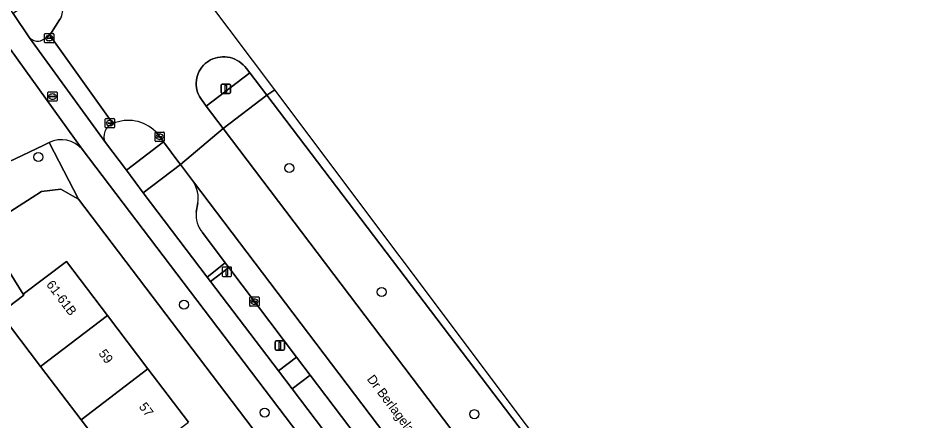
# Model space of a CAD drawing. Extents: x 159664 to 160323, y 385312 to 386115.
# Drawn here: x 160147.9 to 160245, y 385864 to 385907.3 of the extents above; entities that cross this region are included whole.
import ezdxf

# ---------------------------------------------------------------- set-up
doc = ezdxf.new("R2010")
doc.units = 0
for name, color, linetype in [('IMGEO_Berm_groen', 7, 'Continuous'), ('IMGEO_Boom', 7, 'Continuous'), ('IMGEO_Erf', 7, 'Continuous'), ('IMGEO_Fietspad_gesloten', 7, 'Continuous'), ('IMGEO_Kolk', 7, 'Continuous'), ('IMGEO_Laadpaal', 7, 'Continuous'), ('IMGEO_Lichtmast', 7, 'Continuous'), ('IMGEO_Openbare_ruimte_label', 7, 'Continuous'), ('IMGEO_Pand', 7, 'Continuous'), ('IMGEO_Pand_nummerreeks', 7, 'Continuous'), ('IMGEO_Parkeervlak_open', 7, 'Continuous'), ('IMGEO_Rijbaan_lokaal_gesloten', 7, 'Continuous'), ('IMGEO_Rijbaan_lokaal_open', 7, 'Continuous'), ('IMGEO_Rioolput', 7, 'Continuous'), ('IMGEO_Verkeerseiland_groen', 7, 'Continuous'), ('IMGEO_Voetpad_open', 7, 'Continuous')]:
    doc.layers.add(name, color=color, linetype=linetype)

msp = doc.modelspace()

# ---------------------------------------------------------------- linework, layer by layer
at = {"layer": 'IMGEO_Berm_groen'}
for points in [[(160174.614, 385899.039), (160169.921, 385895.45), (160202.923, 385851.883), (160207.751, 385855.425)], [(160170.512, 385880.51), (160168.561, 385878.986), (160175.871, 385869.409), (160177.807, 385870.864)], [(160179.262, 385868.942), (160177.327, 385867.463), (160185.75, 385856.345), (160187.67, 385857.825)]]:
    msp.add_lwpolyline(points, close=True, dxfattribs=at)
for points in [[(160166.706, 385889.723), (160165.321, 385891.586), (160161.323, 385888.557), (160168.182, 385879.472), (160170.13, 385881.015), (160167.67, 385884.268)], [(160167.013, 385886.47), (160167.181, 385887.448)]]:
    msp.add_lwpolyline(points, dxfattribs=at)
for centre, radius, start, end in [((160163.974, 385887.965), 3.249, 350.83368, 32.75318), ((160169.866, 385886.122), 2.874, 173.04987, 220.17667)]:
    msp.add_arc(centre, radius, start, end, dxfattribs=at)
at = {"layer": 'IMGEO_Boom'}
for centre in [(160150.028, 385892.391), (160177.009, 385891.198), (160186.938, 385877.865), (160165.693, 385876.504), (160174.362, 385864.905), (160196.921, 385864.728)]:
    msp.add_circle(centre, 0.489, dxfattribs=at)
at = {"layer": 'IMGEO_Erf'}
for points in [[(160260.143, 385748.478), (160154.34, 385887.843), (160153.697, 385888.214), (160152.472, 385888.921), (160150.373, 385888.694), (160144.032, 385884.624)], [(160145.125, 385882.921), (160148.409, 385877.638), (160153.059, 385881.162), (160157.479, 385875.33), (160161.823, 385869.601), (160166.166, 385863.87)], [(160158.979, 385858.412), (160154.631, 385864.138), (160150.282, 385869.865), (160145.932, 385875.592)]]:
    msp.add_lwpolyline(points, dxfattribs=at)
at = {"layer": 'IMGEO_Fietspad_gesloten'}
msp.add_lwpolyline([(160201.804, 385835.617), (160197.359, 385841.045), (160186.137, 385855.863), (160185.75, 385856.345), (160177.327, 385867.463), (160175.871, 385869.409), (160168.561, 385878.986), (160168.182, 385879.472), (160161.323, 385888.557), (160159.511, 385890.971), (160157.24, 385893.946), (160149.098, 385905.226), (160147.316, 385907.817), (160144.932, 385911.316), (160142.935, 385909.961), (160147.03, 385903.951), (160154.766, 385893.221), (160263.854, 385749.476), (160272.35, 385738.304), (160298.51, 385703.942), (160300.884, 385700.823)], dxfattribs=at)
at = {"layer": 'IMGEO_Kolk'}
for p, q in [((160150.713, 385904.753), (160150.713, 385905.605)), ((160150.788, 385905.679), (160151.64, 385905.679)), ((160151.201, 385905.459), (160151.226, 385905.459)), ((160151.714, 385905.605), (160151.714, 385904.753)), ((160151.64, 385904.679), (160150.788, 385904.679)), ((160150.972, 385905.173), (160150.972, 385905.185)), ((160151.41, 385905.136), (160151.012, 385905.136)), ((160151.015, 385905.222), (160151.413, 385905.222)), ((160151.224, 385904.899), (160151.199, 385904.899)), ((160151.456, 385905.185), (160151.456, 385905.173)), ((160157.237, 385895.612), (160157.237, 385896.464)), ((160157.312, 385896.538), (160158.164, 385896.538)), ((160157.496, 385896.032), (160157.496, 385896.044)), ((160157.934, 385895.995), (160157.536, 385895.995)), ((160157.539, 385896.081), (160157.937, 385896.081)), ((160157.748, 385895.758), (160157.723, 385895.758)), ((160157.725, 385896.318), (160157.75, 385896.318)), ((160157.98, 385896.044), (160157.98, 385896.032)), ((160158.238, 385896.464), (160158.238, 385895.612)), ((160158.164, 385895.538), (160157.312, 385895.538)), ((160162.579, 385894.147), (160162.579, 385894.999)), ((160162.654, 385895.073), (160163.506, 385895.073)), ((160163.067, 385894.853), (160163.092, 385894.853)), ((160163.58, 385894.999), (160163.58, 385894.147)), ((160163.506, 385894.073), (160162.654, 385894.073)), ((160162.838, 385894.567), (160162.838, 385894.579)), ((160163.276, 385894.53), (160162.878, 385894.53)), ((160162.881, 385894.616), (160163.279, 385894.616)), ((160163.09, 385894.293), (160163.065, 385894.293)), ((160163.322, 385894.579), (160163.322, 385894.567)), ((160172.834, 385877.338), (160173.686, 385877.338)), ((160172.759, 385876.412), (160172.759, 385877.264)), ((160173.686, 385876.338), (160172.834, 385876.338)), ((160173.018, 385876.832), (160173.018, 385876.844)), ((160173.456, 385876.795), (160173.058, 385876.795)), ((160173.061, 385876.881), (160173.459, 385876.881)), ((160173.27, 385876.558), (160173.245, 385876.558)), ((160173.247, 385877.118), (160173.272, 385877.118)), ((160173.502, 385876.844), (160173.502, 385876.832)), ((160173.76, 385877.264), (160173.76, 385876.412))]:
    msp.add_line(p, q, dxfattribs=at)
for points in [[(160150.713, 385904.753), (160150.713, 385905.605)], [(160150.788, 385905.679), (160151.64, 385905.679)], [(160151.714, 385905.605), (160151.714, 385904.753)], [(160151.64, 385904.679), (160150.788, 385904.679)], [(160157.237, 385895.612), (160157.237, 385896.464)], [(160157.312, 385896.538), (160158.164, 385896.538)], [(160158.238, 385896.464), (160158.238, 385895.612)], [(160158.164, 385895.538), (160157.312, 385895.538)], [(160162.579, 385894.147), (160162.579, 385894.999)], [(160162.654, 385895.073), (160163.506, 385895.073)], [(160163.58, 385894.999), (160163.58, 385894.147)], [(160163.506, 385894.073), (160162.654, 385894.073)], [(160172.834, 385877.338), (160173.686, 385877.338)], [(160172.759, 385876.412), (160172.759, 385877.264)], [(160173.686, 385876.338), (160172.834, 385876.338)], [(160173.76, 385877.264), (160173.76, 385876.412)]]:
    msp.add_lwpolyline(points, dxfattribs=at)
for centre, radius, start, end in [((160150.79, 385905.603), 0.0765, 91.55205, 178.44795), ((160150.79, 385905.603), 0.0765, 91.55205, 178.44795), ((160151.638, 385905.603), 0.0765, 1.55205, 88.44795), ((160151.638, 385905.603), 0.0765, 1.55205, 88.44795), ((160150.79, 385904.755), 0.0765, 181.55205, 268.44795), ((160150.79, 385904.755), 0.0765, 181.55205, 268.44795), ((160151.012, 385905.182), 0.0403, 85.87752, 175.75265), ((160151.009, 385905.172), 0.0366, 178.93798, 274.71019), ((160151.413, 385905.179), 0.043, 264.86636, 352.45326), ((160151.417, 385905.184), 0.0386, 1.73085, 96.63898), ((160151.638, 385904.755), 0.0765, 271.55205, 358.44795), ((160151.638, 385904.755), 0.0765, 271.55205, 358.44795), ((160157.314, 385896.462), 0.0765, 91.55205, 178.44795), ((160157.314, 385896.462), 0.0765, 91.55205, 178.44795), ((160157.536, 385896.041), 0.0403, 85.87752, 175.75265), ((160157.533, 385896.031), 0.0366, 178.93798, 274.71019), ((160157.937, 385896.038), 0.043, 264.86636, 352.45326), ((160157.941, 385896.043), 0.0386, 1.73085, 96.63898), ((160158.162, 385896.462), 0.0765, 1.55205, 88.44795), ((160158.162, 385896.462), 0.0765, 1.55205, 88.44795), ((160157.314, 385895.614), 0.0765, 181.55205, 268.44795), ((160157.314, 385895.614), 0.0765, 181.55205, 268.44795), ((160158.162, 385895.614), 0.0765, 271.55205, 358.44795), ((160158.162, 385895.614), 0.0765, 271.55205, 358.44795), ((160162.656, 385894.997), 0.0765, 91.55205, 178.44795), ((160162.656, 385894.997), 0.0765, 91.55205, 178.44795), ((160163.504, 385894.997), 0.0765, 1.55205, 88.44795), ((160163.504, 385894.997), 0.0765, 1.55205, 88.44795), ((160162.656, 385894.149), 0.0765, 181.55205, 268.44795), ((160162.656, 385894.149), 0.0765, 181.55205, 268.44795), ((160162.878, 385894.576), 0.0403, 85.87752, 175.75265), ((160162.875, 385894.566), 0.0366, 178.93798, 274.71019), ((160163.279, 385894.573), 0.043, 264.86636, 352.45326), ((160163.283, 385894.578), 0.0386, 1.73085, 96.63898), ((160163.504, 385894.149), 0.0765, 271.55205, 358.44795), ((160163.504, 385894.149), 0.0765, 271.55205, 358.44795), ((160172.836, 385877.262), 0.0765, 91.55205, 178.44795), ((160172.836, 385877.262), 0.0765, 91.55205, 178.44795), ((160173.684, 385877.262), 0.0765, 1.55205, 88.44795), ((160173.684, 385877.262), 0.0765, 1.55205, 88.44795), ((160172.836, 385876.414), 0.0765, 181.55205, 268.44795), ((160172.836, 385876.414), 0.0765, 181.55205, 268.44795), ((160173.058, 385876.841), 0.0403, 85.87752, 175.75265), ((160173.055, 385876.831), 0.0366, 178.93798, 274.71019), ((160173.459, 385876.838), 0.043, 264.86636, 352.45326), ((160173.463, 385876.843), 0.0386, 1.73085, 96.63898), ((160173.684, 385876.414), 0.0765, 271.55205, 358.44795), ((160173.684, 385876.414), 0.0765, 271.55205, 358.44795)]:
    msp.add_arc(centre, radius, start, end, dxfattribs=at)
for centre, major_axis, ratio, start_param, end_param in [((160151.2, 385905.179), (-0.387, 0.002), 0.722429, 4.712389, 7.853982), ((160151.225, 385905.179), (-0.39, 0.002), 0.717154, 1.570796, 4.712389), ((160157.724, 385896.038), (-0.387, 0.002), 0.722429, 4.712389, 7.853982), ((160157.749, 385896.038), (-0.39, 0.002), 0.717154, 1.570796, 4.712389), ((160163.066, 385894.573), (-0.387, 0.002), 0.722429, 4.712389, 7.853982), ((160163.091, 385894.573), (-0.39, 0.002), 0.717154, 1.570796, 4.712389), ((160173.246, 385876.838), (-0.387, 0.002), 0.722429, 4.712389, 7.853982), ((160173.271, 385876.838), (-0.39, 0.002), 0.717154, 1.570796, 4.712389)]:
    msp.add_ellipse(centre, major_axis=major_axis, ratio=ratio, start_param=start_param, end_param=end_param, dxfattribs=at)
at = {"layer": 'IMGEO_Laadpaal'}
for p, q in [((160169.799, 385880.472), (160169.799, 385879.631)), ((160169.799, 385880.472), (160169.799, 385879.631)), ((160170.715, 385880.556), (160169.874, 385880.556)), ((160170.715, 385880.556), (160169.874, 385880.556)), ((160170.799, 385879.64), (160170.799, 385880.481)), ((160170.799, 385879.64), (160170.799, 385880.481)), ((160169.883, 385879.556), (160170.724, 385879.556)), ((160169.883, 385879.556), (160170.724, 385879.556))]:
    msp.add_line(p, q, dxfattribs=at)
msp.add_lwpolyline([(160170.214, 385880.369), (160170.374, 385880.369), (160170.374, 385879.636), (160170.214, 385879.636), (160170.214, 385880.369)], dxfattribs=at)
for centre, start, end in [((160169.877, 385880.478), 92.4484, 184.28452), ((160169.877, 385880.478), 92.4484, 184.28452), ((160170.721, 385880.478), 2.4484, 94.28452), ((160170.721, 385880.478), 2.4484, 94.28452), ((160169.877, 385879.634), 182.4484, 274.28452), ((160169.877, 385879.634), 182.4484, 274.28452), ((160170.721, 385879.634), 272.4484, 4.28452), ((160170.721, 385879.634), 272.4484, 4.28452)]:
    msp.add_arc(centre, 0.0779, start, end, dxfattribs=at)
at = {"layer": 'IMGEO_Lichtmast'}
for p, q in [((160169.695, 385899.339), (160169.695, 385900.139)), ((160169.695, 385900.139), (160169.695, 385899.339)), ((160169.795, 385900.239), (160170.585, 385900.239)), ((160170.585, 385900.239), (160169.795, 385900.239)), ((160170.685, 385900.139), (160170.685, 385899.339)), ((160170.685, 385899.339), (160170.685, 385900.139)), ((160170.585, 385899.239), (160169.795, 385899.239)), ((160169.795, 385899.239), (160170.585, 385899.239)), ((160175.508, 385871.712), (160175.508, 385872.512)), ((160175.508, 385872.512), (160175.508, 385871.712)), ((160175.608, 385872.612), (160176.398, 385872.612)), ((160176.398, 385872.612), (160175.608, 385872.612)), ((160176.498, 385872.512), (160176.498, 385871.712)), ((160176.498, 385871.712), (160176.498, 385872.512)), ((160176.398, 385871.612), (160175.608, 385871.612)), ((160175.608, 385871.612), (160176.398, 385871.612))]:
    msp.add_line(p, q, dxfattribs=at)
for points in [[(160170.115, 385900.114), (160170.265, 385900.114), (160170.265, 385899.364), (160170.115, 385899.364), (160170.115, 385900.114)], [(160175.928, 385872.487), (160176.078, 385872.487), (160176.078, 385871.737), (160175.928, 385871.737), (160175.928, 385872.487)]]:
    msp.add_lwpolyline(points, dxfattribs=at)
for centre, start, end in [((160169.795, 385900.139), 90, 180), ((160169.795, 385900.139), 90, 180), ((160170.585, 385900.139), 0, 90), ((160170.585, 385900.139), 360, 90), ((160169.795, 385899.339), 180, 270), ((160169.795, 385899.339), 180, 270), ((160170.585, 385899.339), 270, 0), ((160170.585, 385899.339), 270, 0), ((160175.608, 385872.512), 90, 180), ((160175.608, 385872.512), 90, 180), ((160176.398, 385872.512), 0, 90), ((160176.398, 385872.512), 360, 90), ((160175.608, 385871.712), 180, 270), ((160175.608, 385871.712), 180, 270), ((160176.398, 385871.712), 270, 0), ((160176.398, 385871.712), 270, 0)]:
    msp.add_arc(centre, 0.1, start, end, dxfattribs=at)
at = {"layer": 'IMGEO_Pand'}
for points in [[(160142.562, 385881.322), (160146.071, 385875.698), (160148.479, 385877.525), (160148.409, 385877.638), (160145.125, 385882.921), (160144.865, 385882.759)], [(160148.479, 385877.525), (160146.071, 385875.698), (160145.932, 385875.592), (160150.282, 385869.865), (160157.479, 385875.33), (160153.059, 385881.162), (160148.409, 385877.638)], [(160161.823, 385869.601), (160157.479, 385875.33), (160150.282, 385869.865), (160154.631, 385864.138)], [(160166.166, 385863.87), (160161.823, 385869.601), (160154.631, 385864.138), (160158.979, 385858.412)]]:
    msp.add_lwpolyline(points, close=True, dxfattribs=at)
at = {"layer": 'IMGEO_Parkeervlak_open'}
for points in [[(160193.92, 385853.82), (160166.706, 385889.723)], [(160167.181, 385887.448), (160167.013, 385886.47)], [(160167.67, 385884.268), (160170.13, 385881.015), (160170.512, 385880.51), (160177.807, 385870.864), (160179.262, 385868.942), (160187.67, 385857.825), (160188.036, 385857.34), (160188.882, 385856.222)]]:
    msp.add_lwpolyline(points, dxfattribs=at)
for centre, radius, start, end in [((160163.974, 385887.965), 3.249, 350.83368, 32.75318), ((160169.866, 385886.122), 2.874, 173.04987, 220.17667)]:
    msp.add_arc(centre, radius, start, end, dxfattribs=at)
at = {"layer": 'IMGEO_Rijbaan_lokaal_gesloten'}
for points in [[(160175.453, 385899.617), (160168.134, 385909.373)], [(160152.489, 385907.443), (160152.41, 385907.282), (160152.316, 385907.13), (160151.454, 385905.785), (160151.23, 385905.547), (160158.05, 385895.988)], [(160162.632, 385895.143), (160163.34, 385894.232), (160163.501, 385894.017), (160165.151, 385891.815), (160165.321, 385891.586), (160169.921, 385895.45), (160168.086, 385897.867), (160167.684, 385898.422), (160167.647, 385898.467), (160167.494, 385898.675), (160167.36, 385898.896), (160167.247, 385899.128), (160167.155, 385899.37), (160167.085, 385899.618), (160167.037, 385899.872), (160167.012, 385900.129), (160167.01, 385900.388), (160167.032, 385900.645), (160167.076, 385900.899), (160167.142, 385901.149), (160167.231, 385901.392), (160167.341, 385901.625), (160167.472, 385901.848), (160167.622, 385902.058), (160167.79, 385902.255), (160167.975, 385902.435), (160168.175, 385902.598), (160168.318, 385902.695), (160168.552, 385902.83), (160168.797, 385902.944), (160169.052, 385903.035), (160169.313, 385903.103), (160169.58, 385903.147), (160169.85, 385903.168), (160170.12, 385903.164), (160170.389, 385903.137), (160170.654, 385903.085), (160170.914, 385903.01), (160171.166, 385902.912), (160171.408, 385902.791), (160171.638, 385902.65), (160171.855, 385902.489), (160172.057, 385902.309), (160172.242, 385902.111), (160172.408, 385901.898), (160172.762, 385901.456), (160174.614, 385899.039), (160175.453, 385899.617)]]:
    msp.add_lwpolyline(points, dxfattribs=at)
for points in [[(160278.119, 385766.625), (160272.577, 385773.993), (160202.503, 385863.561), (160175.453, 385899.617), (160174.614, 385899.039), (160207.751, 385855.425), (160209.198, 385853.52), (160209.222, 385853.486), (160218.049, 385841.864), (160218.207, 385841.662), (160220.49, 385838.634), (160222.308, 385836.246), (160276.21, 385765.273)], [(160169.921, 385895.45), (160165.321, 385891.586), (160166.706, 385889.723), (160193.92, 385853.82), (160202.671, 385842.281), (160205.159, 385839.046), (160210.857, 385831.546), (160212.699, 385829.104), (160214.504, 385826.716), (160264.977, 385760.314), (160266.788, 385757.939), (160271.472, 385761.661), (160217.534, 385832.65), (160215.717, 385835.043), (160213.549, 385837.897), (160213.521, 385837.931), (160204.43, 385849.882), (160204.376, 385849.964), (160202.923, 385851.883)]]:
    msp.add_lwpolyline(points, close=True, dxfattribs=at)
msp.add_arc((160159.712, 385892.152), 4.18, 45.68208, 113.42005, dxfattribs=at)
at = {"layer": 'IMGEO_Rijbaan_lokaal_open'}
for points in [[(160158.05, 385895.988), (160151.23, 385905.547)], [(160149.098, 385905.226), (160157.24, 385893.946)], [(160154.766, 385893.221), (160147.03, 385903.951)], [(160142.267, 385889.736), (160148.284, 385892.569), (160150.619, 385893.683), (160151.188, 385893.955)]]:
    msp.add_lwpolyline(points, dxfattribs=at)
for centre, radius, start, end in [((160149.565, 385907.008), 2.215, 283.91803, 318.73615), ((160150.004, 385906.144), 1.29, 225.40095, 274.19182), ((160158.551, 385894.608), 1.469, 109.95207, 206.77446), ((160152.497, 385891.25), 3.005, 40.98436, 115.82971)]:
    msp.add_arc(centre, radius, start, end, dxfattribs=at)
at = {"layer": 'IMGEO_Rioolput'}
for p, q in [((160151.056, 385898.47), (160151.056, 385899.322)), ((160151.131, 385899.396), (160151.983, 385899.396)), ((160151.315, 385898.89), (160151.315, 385898.902)), ((160151.753, 385898.853), (160151.355, 385898.853)), ((160151.358, 385898.939), (160151.756, 385898.939)), ((160151.544, 385899.176), (160151.569, 385899.176)), ((160151.799, 385898.902), (160151.799, 385898.89)), ((160152.057, 385899.322), (160152.057, 385898.47)), ((160151.983, 385898.396), (160151.131, 385898.396)), ((160151.567, 385898.616), (160151.542, 385898.616))]:
    msp.add_line(p, q, dxfattribs=at)
for points in [[(160151.056, 385898.47), (160151.056, 385899.322)], [(160151.131, 385899.396), (160151.983, 385899.396)], [(160152.057, 385899.322), (160152.057, 385898.47)], [(160151.983, 385898.396), (160151.131, 385898.396)]]:
    msp.add_lwpolyline(points, dxfattribs=at)
for centre, radius, start, end in [((160151.133, 385899.32), 0.0765, 91.55205, 178.44795), ((160151.133, 385899.32), 0.0765, 91.55205, 178.44795), ((160151.355, 385898.899), 0.0403, 85.87752, 175.75265), ((160151.352, 385898.889), 0.0366, 178.93798, 274.71019), ((160151.756, 385898.896), 0.043, 264.86636, 352.45326), ((160151.76, 385898.901), 0.0386, 1.73085, 96.63898), ((160151.981, 385899.32), 0.0765, 1.55205, 88.44795), ((160151.981, 385899.32), 0.0765, 1.55205, 88.44795), ((160151.133, 385898.472), 0.0765, 181.55205, 268.44795), ((160151.133, 385898.472), 0.0765, 181.55205, 268.44795), ((160151.981, 385898.472), 0.0765, 271.55205, 358.44795), ((160151.981, 385898.472), 0.0765, 271.55205, 358.44795)]:
    msp.add_arc(centre, radius, start, end, dxfattribs=at)
for centre, major_axis, ratio, start_param, end_param in [((160151.543, 385898.896), (-0.387, 0.002), 0.722429, 4.712389, 7.853982), ((160151.568, 385898.896), (-0.39, 0.002), 0.717154, 1.570796, 4.712389)]:
    msp.add_ellipse(centre, major_axis=major_axis, ratio=ratio, start_param=start_param, end_param=end_param, dxfattribs=at)
at = {"layer": 'IMGEO_Verkeerseiland_groen'}
for points in [[(160152.41, 385907.282), (160152.489, 385907.443), (160152.554, 385907.609), (160152.604, 385907.781), (160152.638, 385907.956), (160152.657, 385908.134), (160152.659, 385908.313), (160152.646, 385908.491), (160152.616, 385908.668), (160152.571, 385908.841), (160152.511, 385909.009), (160152.436, 385909.171), (160152.347, 385909.326), (160152.309, 385909.383), (160151.457, 385910.646), (160147.316, 385907.817), (160149.098, 385905.226)], [(160151.23, 385905.547), (160151.454, 385905.785), (160152.316, 385907.13), (160152.41, 385907.282)], [(160157.24, 385893.946), (160159.511, 385890.971), (160163.501, 385894.017), (160163.34, 385894.232), (160162.632, 385895.143)]]:
    msp.add_lwpolyline(points, dxfattribs=at)
msp.add_lwpolyline([(160172.408, 385901.898), (160172.242, 385902.111), (160172.057, 385902.309), (160171.855, 385902.489), (160171.638, 385902.65), (160171.408, 385902.791), (160171.166, 385902.912), (160170.914, 385903.01), (160170.654, 385903.085), (160170.389, 385903.137), (160170.12, 385903.164), (160169.85, 385903.168), (160169.58, 385903.147), (160169.313, 385903.103), (160169.052, 385903.035), (160168.797, 385902.944), (160168.552, 385902.83), (160168.318, 385902.695), (160168.175, 385902.598), (160167.975, 385902.435), (160167.79, 385902.255), (160167.622, 385902.058), (160167.472, 385901.848), (160167.341, 385901.625), (160167.231, 385901.392), (160167.142, 385901.149), (160167.076, 385900.899), (160167.032, 385900.645), (160167.01, 385900.388), (160167.012, 385900.129), (160167.037, 385899.872), (160167.085, 385899.618), (160167.155, 385899.37), (160167.247, 385899.128), (160167.36, 385898.896), (160167.494, 385898.675), (160167.647, 385898.467), (160167.684, 385898.422), (160168.086, 385897.867), (160172.762, 385901.456)], close=True, dxfattribs=at)
for centre, radius, start, end in [((160149.565, 385907.008), 2.215, 283.91803, 318.73615), ((160150.004, 385906.144), 1.29, 225.40095, 274.19182), ((160158.551, 385894.608), 1.469, 109.95207, 206.77446), ((160159.712, 385892.152), 4.18, 45.68208, 113.42005)]:
    msp.add_arc(centre, radius, start, end, dxfattribs=at)
at = {"layer": 'IMGEO_Voetpad_open'}
for points in [[(160174.614, 385899.039), (160172.762, 385901.456), (160168.086, 385897.867), (160169.921, 385895.45)], [(160163.501, 385894.017), (160159.511, 385890.971), (160161.323, 385888.557), (160165.321, 385891.586), (160165.151, 385891.815)], [(160170.13, 385881.015), (160168.182, 385879.472), (160168.561, 385878.986), (160170.512, 385880.51)], [(160177.327, 385867.463), (160179.262, 385868.942), (160177.807, 385870.864), (160175.871, 385869.409)]]:
    msp.add_lwpolyline(points, close=True, dxfattribs=at)
for points in [[(160143.816, 385884.486), (160144.032, 385884.624), (160150.373, 385888.694), (160152.472, 385888.921), (160153.697, 385888.214), (160154.34, 385887.843), (160151.188, 385893.955), (160150.619, 385893.683), (160148.284, 385892.569), (160142.267, 385889.736), (160142.848, 385888.812), (160116.954, 385872.646), (160116.374, 385873.568), (160115.451, 385872.983), (160113.391, 385871.684)], [(160151.188, 385893.955), (160154.34, 385887.843), (160260.143, 385748.478), (160263.491, 385744.011)], [(160263.854, 385749.476), (160154.766, 385893.221)]]:
    msp.add_lwpolyline(points, dxfattribs=at)
msp.add_arc((160152.497, 385891.25), 3.005, 40.98436, 115.82971, dxfattribs=at)

# ---------------------------------------------------------------- texts
at = {"layer": 'IMGEO_Openbare_ruimte_label'}
msp.add_text('Dr Berlagelaan', height=1, rotation=307.15637, dxfattribs=at).set_placement((160185.314, 385868.492))
at = {"layer": 'IMGEO_Pand_nummerreeks'}
for s, rotation, p in [('61-61B', 307.15803, (160150.84, 385878.66)), ('59', 307.16212, (160156.458, 385871.247)), ('57', 307.16212, (160160.8, 385865.52))]:
    msp.add_text(s, height=1, rotation=rotation, dxfattribs=at).set_placement(p)

doc.saveas('drawing.dxf')
